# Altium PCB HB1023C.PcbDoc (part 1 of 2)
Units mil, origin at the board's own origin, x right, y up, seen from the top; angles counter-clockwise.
Board outline 1895.03 x 2760.94 mil, 2 copper layers (Top Layer, Bottom Layer); 83 components, 64 nets, 266 pads, 261 vias.
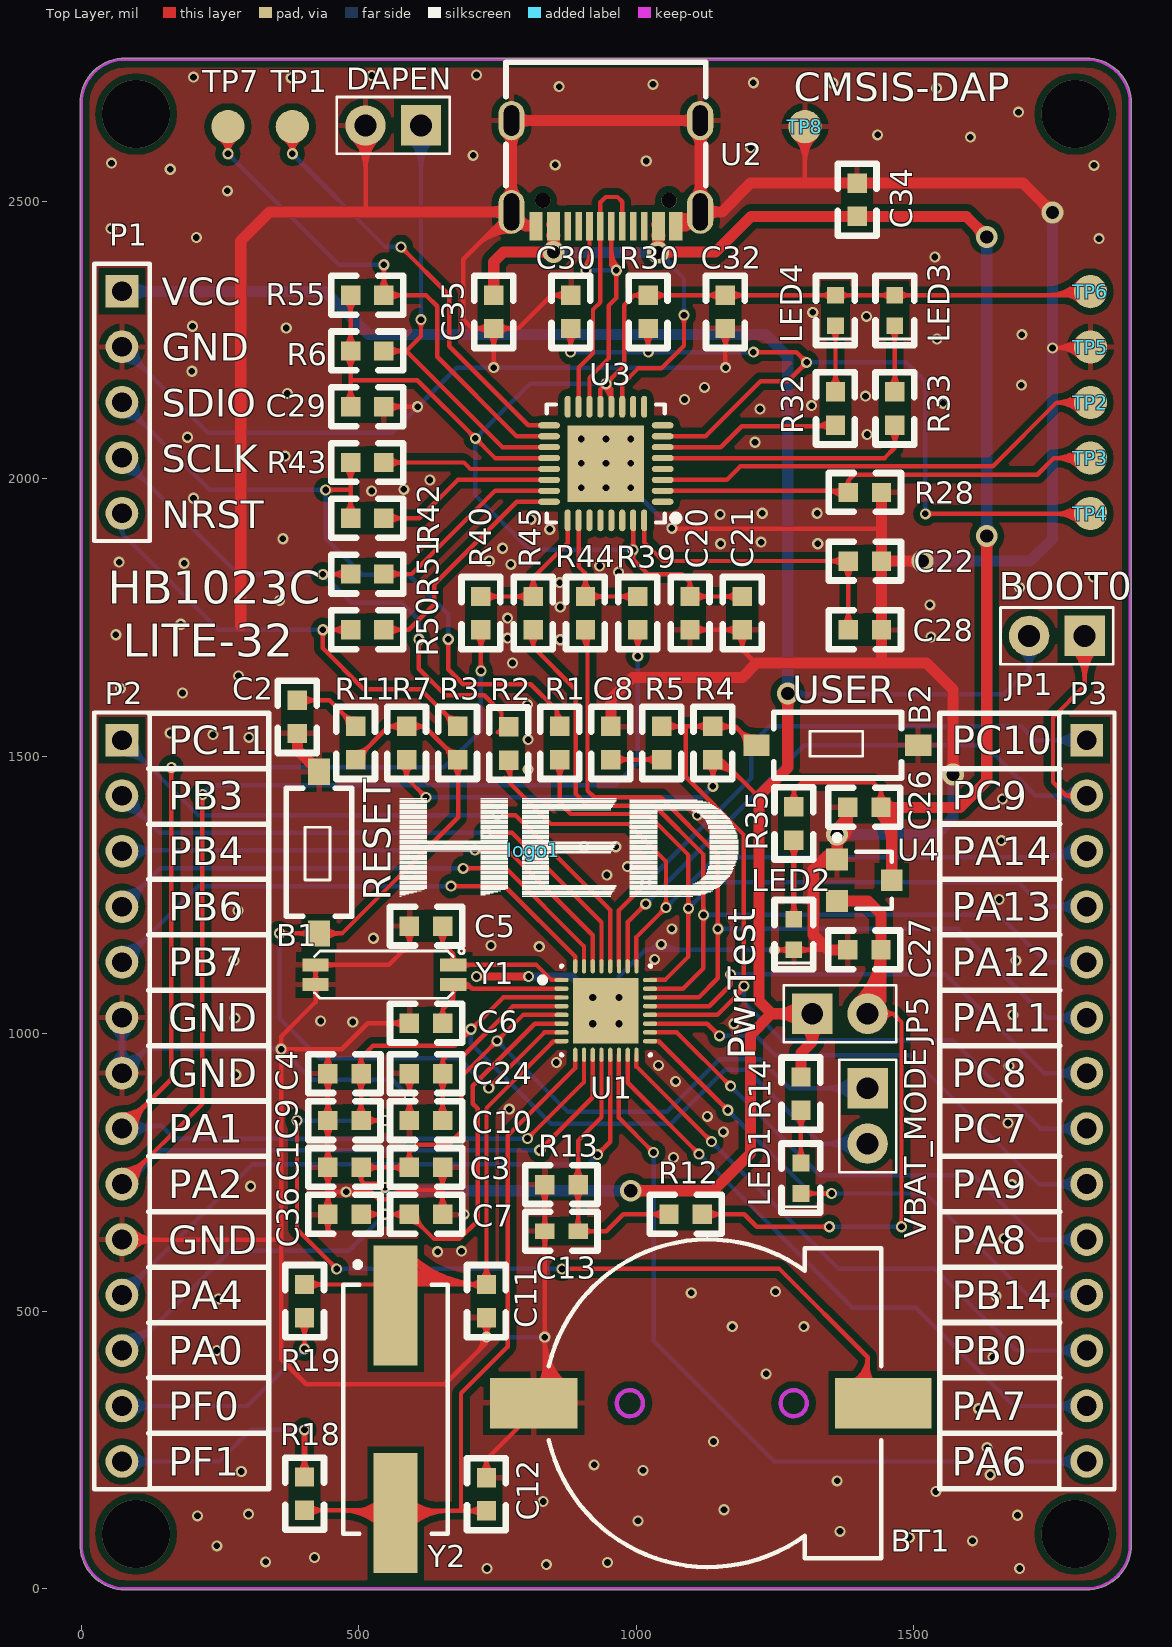
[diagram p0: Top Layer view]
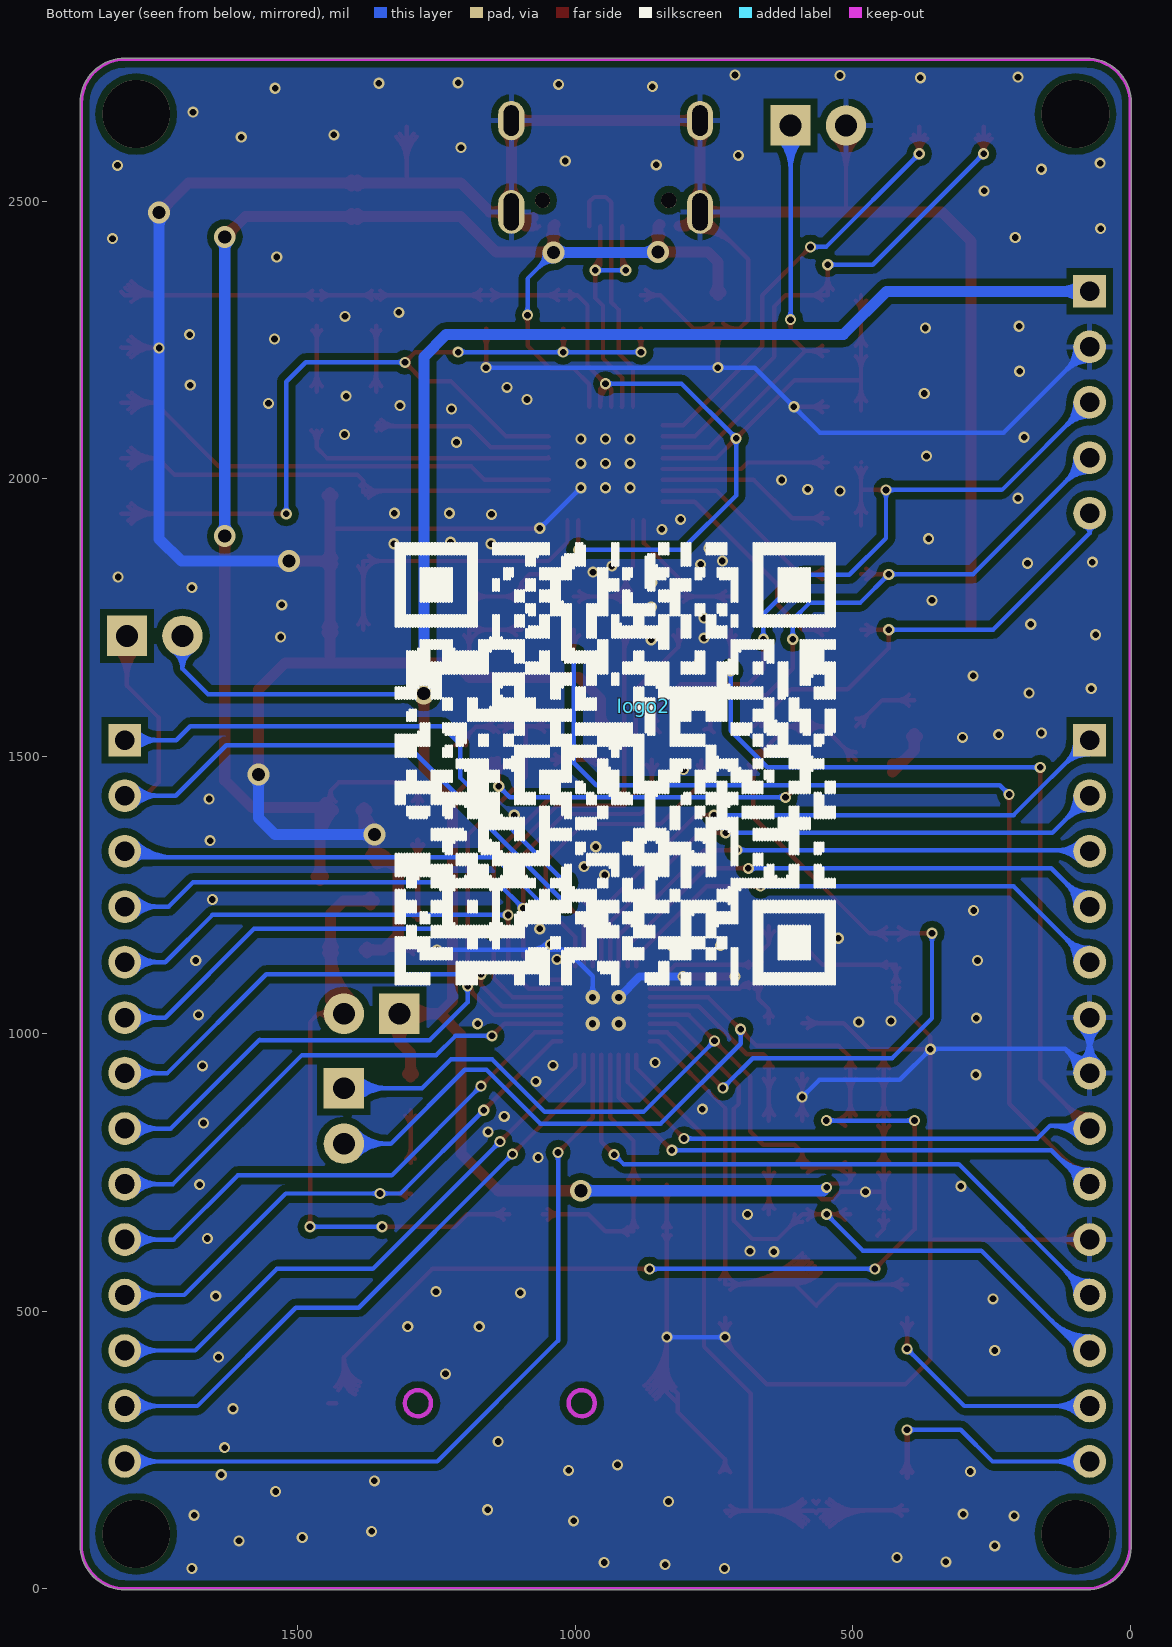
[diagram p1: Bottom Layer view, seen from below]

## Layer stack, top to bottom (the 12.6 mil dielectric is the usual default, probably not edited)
Top Layer: signal copper 1.4
Dielectric: dielectric 12.6, FR-4, Dk 4.8
Bottom Layer: signal copper 1.4

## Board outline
77.95,-2.51 ccw(c78,0) 78.37,-2.49 ccw(c78.74,0) 78.74,-2.51 1811.02,-2.51 ccw(c1811,79) 1892.52,79 ccw(c1890,79) 1892.28,80.06 1892.28,2676.72 ccw(c1889.8,2677.17) 1892.32,2677.17 ccw(c1811.06,2677.17) 1811.06,2758.42 ccw(c1811.06,2755.91) 1811.05,2758.42 ccw(c1811.02,2755.91) 1811.02,2758.42 78.74,2758.42 ccw(c78.74,2677.17) -2.52,2677.17 ccw(c0,2677.17) -2.51,2677.14 -2.51,81.02 cw(c79.5,79.5) -2.51,81.05 -2.51,81.02 ccw(c79.5,79.5)

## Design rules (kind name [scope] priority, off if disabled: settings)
Clearance [(IsPad and InComponent('U1'))] p1: gap=7
Clearance Clearance_poly [(InPolygon)] p2: gap=12
Clearance Clearance_CN [(IsPad and InComponent('P2','P3','U2'))] p3: gap=6
Clearance Clearance_Pad [All] p4: gap=7
ComponentClearance [All] p1: gap=0 collisioncheckmode=3 verticalgap=0 showdistances=FALSE
HoleSize [All] p1: absolutevalues=TRUE maxlimit=130 minlimit=1 maxpercent=80.000 minpercent=20.000
MinimumSolderMaskSliver [All] p1: minsoldermaskwidth=0
PolygonConnect PolygonConnect_Pads [IsPad] p1: connectstyle=Relief reliefconductorwidth=10 reliefentries=4 polygonreliefangle="90 Angle"
PolygonConnect [All] p2: connectstyle=Direct reliefconductorwidth=10 reliefentries=4 polygonreliefangle="90 Angle"
RoutingVias [All] p1: holewidth=12 width=20 viastyle="Through Hole" minholewidth=10 minwidth=18 maxholewidth=300 maxwidth=500
SilkToSilkClearance [All] p1: silktosilkclearance=0
SilkscreenOverComponentPads [IsPad] p1: minsilkscreentomaskgap=0
SolderMaskExpansion [All] p1: expansion=4
TestPointUsage [All] p1: valid=0 allowmultiple=FALSE
Testpoint [(IsPad And (OnTopLayer Or OnBottomLayer))] p1: side=3 testpointundercomponent=TRUE minsize=40 maxsize=100 preferedsize=60 minholesize=0 maxholesize=40 preferedholesize=32 testpointgrid=1 style=297 order=0-112345678
Width [All] p1: maxlimit=20 minlimit=8 preferedwidth=8
19 further rules are at their usual default settings.

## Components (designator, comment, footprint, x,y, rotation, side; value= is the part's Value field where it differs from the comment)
B1 "TS-1101-C-W" 按键_TS-1101-C-W 428,1472 r270 top
B2 "TS-1101-C-W" 按键_TS-1101-C-W 1508,1519.94 r180 top
BT1 "CR1220电池座" CR1220 1445.05,334 r180 top
C1 "10u" 0603#1 444,759 r0 top
C2 "0.1u" 0603#1 389,1601 r270 top
C3 "0.1u" 0603#1 651,759 r180 top
C4 "1u" 0603#1 444,928 r0 top
C5 "10p" 0603#1 591,1194 r0 top
C6 "10p" 0603#1 591,1019 r0 top
C7 "1u" 0603#1 651,674.5 r180 top
C8 "0.1u" 0603#1 954,1554 r270 top
C9 "0.1u" 0603#1 444,843.5 r0 top
C10 "1u" 0603#1 651,843.5 r180 top
C11 "DNP" 0603#1 730,548 r270 top
C12 "DNP" 0603#1 730,140 r90 top
C13 "0.1u" 0603#2 835,644 r0 top
C20 "1u" 0603#1 1096.8,1728 r90 top
C21 "10n" 0603#1 1191,1728 r90 top
C22 "4.7u" 0603#1 1442,1851.75 r180 top
C24 "0.1u" 0603#1 651,928 r180 top
C26 "10u" 0603#1 1381,1408 r0 top
C27 "10u" 0603#1 1381,1151 r0 top
C28 "0.1u" 0603#1 1442,1728 r180 top
C29 "0.1u" 0603#1 545,2130 r180 top
C30 "0.1u" 0603#1 882.17,2271 r90 top
C32 "1u" 0603#1 1160.5,2331 r270 top
C34 "0.1u" 0603#1 1398,2533 r270 top
C35 "1u" 0603#1 743,2331 r270 top
C36 "0.1u" 0603#1 444,674.5 r0 top
DAPEN "Header 1x2" HEADER_1X2_2.54 562,2637 r180 top
JP1 "Header 1x2" HEADER_1X2_2.54 1758,1717 r180 top
JP5 "Header 1x2" HEADER_1X2_2.54 1367,1036 r0 top
LED1 "LED_G" "0603 - p" 1296.78,767 r270 top
LED2 "LED_R" 0603-P 1284,1206 r270 top
LED3 "LED_G" 0603-P 1466,2331 r270 top
LED4 "LED_R" 0603-P 1359,2331 r270 top
logo1 "logo" LOGO 815,1331 r0 top
logo2 "SIGN" SIGN 877,1590 r270 bottom locked
P1 "Header 1x5" HDR1X5_2.54 73,2338 r270 top
P2 "Header 14" HDR1X14 73,1529 r270 top
P3 "Header 14" HDR1X14 1812,1529 r270 top
R1 "470R" 0603#1 862,1494 r90 top
R2 "470R" 0603#1 770,1493 r90 top
R3 "470R" 0603#1 678,1494 r90 top
R4 "4.7k" 0603#1 1138,1554 r270 top
R5 "10R" 0603#1 1046,1494 r90 top
R6 "4.7K" 0603#1 545,2230.5 r180 top
R7 "10K" 0603#1 586,1494 r90 top
R11 "10R" 0603#1 494,1494 r90 top
R12 "10K" 0603#1 1059,674.5 r0 top
R13 "10K" 0603#1 895,728 r180 top
R14 "510R" 0603#1 1296.78,862 r90 top
R18 "0R" 0603#1 402,141 r90 top
R19 "0R" 0603#1 402,548 r270 top
R28 "DNP" 0603#1 1442,1975.5 r180 top
R30 "DNP" 0603#1 1021.33,2331 r270 top
R32 "1K" 0603#1 1359,2097 r90 top
R33 "1K" 0603#1 1466,2097 r90 top
R35 "1K" 0603#1 1284,1349 r90 top
R39 "0R" 0603#1 1002.6,1788 r270 top
R40 "0R" 0603#1 720,1788 r270 top
R42 "150R" 0603#1 545,1929 r180 top
R43 "150R" 0603#1 545,2029.5 r180 top
R44 "DNP" 0603#1 908.4,1788 r270 top
R45 "DNP" 0603#1 814.2,1788 r270 top
R50 "150R" 0603#1 545,1728 r180 top
R51 "150R" 0603#1 545,1828.5 r180 top
R55 "4.7K" 0603#1 485,2331 r0 top
TP1 "TEST_POINT" TEST_POINT 385,2672.78 r90 top
TP2 "TEST_POINT" TEST_POINT 1823.45,2175.5 r90 top
TP3 "TEST_POINT" TEST_POINT 1823.45,2075.5 r90 top
TP4 "TEST_POINT" TEST_POINT 1823.45,1975.5 r90 top
TP5 "TEST_POINT" TEST_POINT 1823.45,2275.5 r90 top
TP6 "TEST_POINT" TEST_POINT 1823.45,2375.5 r90 top
TP7 "TEST_POINT" TEST_POINT 226,2639.78 r180 top
TP8 "TEST_POINT" TEST_POINT 1309,2672.78 r90 top
U1 "" QFN_32N_4X4 945.13,1041.72 r0 top locked
U2 "TYPE-C-16P" HED-KH-TYPE-C-16P 1115.25,2481.06 r180 top locked
U3 "CIU98_H" HED-QFN-32_5x5x05P 945.16,2027.64 r90 top locked
U4 "ME6210A33M3G" SOT-23-3 1407,1279 r270 top
VBAT_MODE "Header 1x2" HEADER_1X2_2.54 1417,851.78 r270 top
Y1 "M6-32.768KHz 12.5pF" XTAL-MC146 670,1123.93 r180 top
Y2 "DNP" XTAL_HC49/SMD 566,323 r270 top

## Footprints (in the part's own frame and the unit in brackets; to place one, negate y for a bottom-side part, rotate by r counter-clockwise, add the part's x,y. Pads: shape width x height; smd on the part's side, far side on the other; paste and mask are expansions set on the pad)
0603#1 [mil]
  rect 35x35 smd: 1(0,0) 2(60,0)
  silkscreen extent -35,-35 95,35
0603#2 [mil]
  rect 35x27.56 smd: 1(0,0) 2(60,0)
  silkscreen extent -35,-35 95,35
"0603 - p" [mil]
  rect 30x30 smd: 1(0,0) 2(55,0)
  silkscreen extent -35,-35 90,35, body extent 1,-15 60,15, height 10
0603-P [mil]
  rect 30x30 smd: 1(0,0) 2(55,0)
  silkscreen extent -35,-35 90,35, body extent 1,-15 60,15, height 10
CR1220 [mm]
  rect 4.4x2.3 smd: 1(0,0)
  rect 4x2.3 smd: 2(16,0)
  Keep-Out Layer circle w0.203: c11.6,0 r0.6
  Keep-Out Layer circle w0.203: c4.1,0 r0.6
  silkscreen extent 0.1,-7.5 15.31,7.5
HDR1X5_2.54 [mm]
  rect 1.5x1.5 hole 0.9: 1(0,0)
  round 1.5 hole 0.9: 2(2.54,0) 3(5.08,0) 4(7.62,0) 5(10.16,0)
  silkscreen extent -1.27,-1.27 11.43,1.27
HDR1X14 [mm] "Connector; Header; 14 Position"
  rect 1.5x1.5 hole 0.9: 1(0,0)
  round 1.5 hole 0.9: 2(2.54,0) 3(5.08,0) 4(7.62,0) 5(10.16,0) 6(12.7,0) 7(15.24,0) 8(17.78,0) 9(20.32,0) 10(22.86,0) 11(25.4,0) 12(27.94,0) 13(30.48,0) 14(33.02,0)
  silkscreen extent -1.27,-1.27 34.29,1.27
HEADER_1X2_2.54 [mm]
  rect 1.85x1.85 / inner round 1.85 / far side rect 1.85x1.85 hole 1: 1(-1.27,0)
  round 1.85 hole 1: 2(1.27,0)
  silkscreen extent -2.58,-1.3 2.58,1.3, body extent -2.67,-1.3 2.58,1.3, height 8.38
HED-KH-TYPE-C-16P [mm]
  oval 1.2x2 hole 0.7 slot 1.7 at 90 deg: 1(0,0) 2(8.64,0)
  oval 1.2x1.8 hole 0.7 slot 1.4 at 90 deg: 3(0,-4.18) 4(8.64,-4.18)
  rect 0.3x1.3 smd: A1(0.97,0.65) A4(1.77,0.65) A5(3.07,0.65) A6(4.07,0.65) A7(4.57,0.65) A8(5.57,0.65) A9(6.87,0.65) A12(7.67,0.65) B1(7.37,0.65) B4(6.57,0.65) B5(6.07,0.65) B6(5.07,0.65) B7(3.57,0.65) B8(2.57,0.65) B9(2.07,0.65) B12(1.27,0.65)
  round 0.7 hole 0.7 unplated: ""(1.43,-0.53) ""(7.21,-0.53)
  silkscreen extent -0.25,-6.84 8.89,-1.19
HED-QFN-32_5x5x05P [mm]
  oval 0.28x1 smd: 1(-1.75,-2.6) 2(-1.25,-2.6) 3(-0.75,-2.6) 4(-0.25,-2.6) 5(0.25,-2.6) 6(0.75,-2.6) 7(1.25,-2.6) 8(1.75,-2.6) 17(1.75,2.6) 18(1.25,2.6) 19(0.75,2.6) 20(0.25,2.6) 21(-0.25,2.6) 22(-0.75,2.6) 23(-1.25,2.6) 24(-1.75,2.6)
  oval 1x0.28 smd: 9(2.6,-1.75) 10(2.6,-1.25) 11(2.6,-0.75) 12(2.6,-0.25) 13(2.6,0.25) 14(2.6,0.75) 15(2.6,1.25) 16(2.6,1.75) 25(-2.6,1.75) 26(-2.6,1.25) 27(-2.6,0.75) 28(-2.6,0.25) 29(-2.6,-0.25) 30(-2.6,-0.75) 31(-2.6,-1.25) 32(-2.6,-1.75)
  rect 3.5x3.5 smd: 33(0,0)
  silkscreen extent -2.7,-3.35 2.7,2.7
LOGO [mil]
  silkscreen extent -241,-83 369,93
QFN_32N_4X4 [mm]
  oval 0.65x0.2 smd: 1(-2.025,1.4) 2(-2.025,1) 3(-2.025,0.6) 4(-2.025,0.2) 5(-2.025,-0.2) 6(-2.025,-0.6) 7(-2.025,-1) 8(-2.025,-1.4) 17(2.025,-1.4) 18(2.025,-1) 19(2.025,-0.6) 20(2.025,-0.2) 21(2.025,0.2) 22(2.025,0.6) 23(2.025,1) 24(2.025,1.4)
  oval 0.2x0.65 smd: 9(-1.4,-2.025) 10(-1,-2.025) 11(-0.6,-2.025) 12(-0.2,-2.025) 13(0.2,-2.025) 14(0.6,-2.025) 15(1,-2.025) 16(1.4,-2.025) 25(1.4,2.025) 26(1,2.025) 27(0.6,2.025) 28(0.2,2.025) 29(-0.2,2.025) 30(-0.6,2.025) 31(-1,2.025) 32(-1.4,2.025)
  rect 3x3 smd: 33(0,0)
  silkscreen extent -3.02,-2.05 2.05,2.05, body extent -2.05,-2.05 2.05,2.05, height 0.8
SIGN [mil]
  silkscreen extent -294,-446 501,344
SOT-23-3 [mm]
  rect 1x1 smd: 1(-0.889,-1.143) 2(1.011,-1.143) 3(0.061,1.357)
  silkscreen extent -2.01,-1.27 1.36,1.36, body extent -1.39,-1.29 1.51,1.51, height 1.2
TEST_POINT [mil]
  round 60 smd: 1(-38,5)
XTAL-MC146 [mm]
  rect 1.2x0.6 smd mask+0.05: 1(0,0) 2(6.3,0) 3(6.3,0.9) 4(0,0.9)
  silkscreen extent -0.51,-0.76 6.35,1.52
XTAL_HC49/SMD [mm]
  rect 5.5x2 smd: 1(-4.75,0) 2(4.75,0)
  silkscreen extent -6.75,-2.4 5.7,2.4, body extent -6.7,-2.46 6.7,2.44, height 4
按键_TS-1101-C-W [mm] "星坤品牌"
  rect 1.2x1 smd mask+0.05: 1(0,0) 2(7.4,0)
  silkscreen extent 0.76,-1.5 6.6,1.5

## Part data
B1 U1: library part CIU32L051Kx-QFN32
B2: library part SW-PB, "贴片按键"
BT1: library part Battery, "Multicell Battery"
C1 C13 C36: library part MCD-00009, "Capacitor, MLCC, 4.7uF, 16V, X5R, 10%, 0603, T=0.8mm"
C2 C3 C4 C7 C9 C11 C20 C21 C22 C30 C32 C35: library part MCD-00211, "Capacitor, MLCC, 100nF, 16V, X7R, 10%, 0603, T=0,8mm"
C5 C6: library part MCD-00666, "Capacitor,5.6pF,0.1pF,16V,NPO,0603"
C8: library part MCD-00211, "贴片电容"
C10 C12: library part MCD-00009, "贴片电容33p"
C24 C26: library part MCD-00014, "Capacitor, MLCC, 10uF, 25V, X5R, 10%, 0805, T=0,85mm"
C27 P1: library part SWD, "Header, 1x5, 2,54mm, VR, TH, Height 5.84mm/2.54mm"
C28 C29: library part "Header 14", "Header, 14-Pin"
C34: library part "0603 100nF 10% 50V", "贴片电容"
DAPEN: library part MCD-00683, "Header, 2x1, 2,54mm, VR, TH, Height 5.84mm/2.54mm"
JP1 JP5 VBAT_MODE: library part MCD-00683, "Header, 2x1, 2,54mm, VR, TH, Height 5.84mm/2.54mm - Shunt Fitted by default"
LED1 LED3: library part LED1, "贴片LED 绿色"
LED2 LED4: library part LED1, "贴片LED 红色"
P2 P3: "Header, 14-Pin"
R1 R2 R3 R6 R28 R42 R43 R50 R51 R55: library part Res, "贴片电阻"
R4 R5 R7 R11 R12 R13 R14 R18 R19 R30 R32 R33 R35 R39 R40 R44 R45: library part Res2, "贴片电阻"
U2: library part KH-TYPE-C-16P, "TYPE-C USB接口"
U3: library part CIU98-H, "贴片芯片"
U4: library part ME6210, "贴片LDO3.3V"
Y1: library part MC146, "贴片晶振"
Y2: library part XTAL_32K_NX3215SA, "Crystal 32.768kHz, 6pF, -+20PPM, R=50K, SMD"

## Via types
v1: diameter 20, hole 12, Top Layer to Bottom Layer, tented both sides, 243 vias
v2: diameter 39.37, hole 23.62, Top Layer to Bottom Layer, tented both sides, 10 vias
v3: diameter 122.05, hole 122.05, Top Layer to Bottom Layer, tented both sides, 4 vias
v4: diameter 25.98, hole 12.99, Top Layer to Bottom Layer, 4 vias

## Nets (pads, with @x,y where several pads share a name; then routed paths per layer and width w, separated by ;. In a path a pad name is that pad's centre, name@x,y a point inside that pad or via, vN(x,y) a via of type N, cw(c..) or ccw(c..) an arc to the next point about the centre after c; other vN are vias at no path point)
CMS_STATE: TP1.1 U3.17 | length 967.8
  Top Layer w8: TP1.1@365.51,2613.19 cw(c347.25,2586) v1(380,2586) ; TP1.1@369.97,2619.84 cw(c357.33,2601.01) 380,2601.01 cw(c402.68,2601.01) TP1.1@390.03,2619.84 ; v1@375.76,2590.24 ccw(c365.51,2600.49) 380,2600.49 ccw(c394.48,2600.48) v1@384.24,2590.24 ; TP1.1@380,2634.78 v1(380,2586) ; TP1.1@394.49,2613.19 ccw(c412.75,2586) v1(380,2586) ; v1@576,2412 cw(c576,2397.51) 586.24,2407.76 cw(c596.49,2418) v1@582,2418 ; v1(576,2418) 663,2331 663,2239 805.46,2096.54 U3.17@842.8,2096.54
  Bottom Layer w8: v1@380,2580 cw(c380,2565.51) 390.24,2575.76 cw(c400.49,2586) v1@386,2586 ; v1(380,2586) 548,2418 v1(576,2418) ; v1@571.76,2413.76 ccw(c561.51,2403.51) 561.51,2418 ccw(c561.51,2432.49) v1@571.76,2422.24
GND: B1.1 B2.1 BT1.2 C1.1 C2.2 C3.1 C4.1 C5.1 C6.1 C7.1 C8.1 C9.1 C10.2 C11.2 C12.2 C13.1 C20.1 C21.1 C22.1 C24.2 C26.1 C27.1 C28.1 C29.1 C30.2 C32.2 C34.1 C35.2 C36.1 DAPEN.2 LED2.2 P1.2 P2.6 P2.7 P2.10 R13.2 R28.1 TP5.1 TP8.1 U1.33 U2.1 U2.2 U2.3 U2.4 U2.A1 U2.A12 U2.B1 U2.B12 U3.33 U4.1 Y1.2 Y1.3 | length 18990.4
  Top Layer w8: P2.10@66,629 P2.10@73,629 ; P2.6@73,1029 P2.6@76,1032 ; P2.10@74,629 P2.10@73,629 ; P2.10@85.39,616.61 cw(c115.32,586.68) 115.32,629 cw(c115.32,671.32) P2.10@85.39,641.39 ; P2.10@91.05,610.95 cw(c134.63,567.37) 134.63,629 cw(c134.63,690.63) P2.10@91.05,647.05 ; v1@355.69,967.76 cw(c345.45,957.51) 359.93,957.51 cw(c374.42,957.51) 364.17,967.76 cw(c374.42,957.51) 374.42,972 cw(c374.42,986.49) 364.17,976.24 cw(c374.42,986.49) 359.93,986.49 cw(c345.45,986.49) v1@355.69,976.24 ; Y1.3@416.45,1082.98 cw(c403.11,1069.64) 421.97,1069.64 cw(c440.83,1069.64) Y1.3@427.49,1082.98 ; Y1.3@416.45,1094.02 ccw(c403.11,1107.36) 421.97,1107.36 ccw(c440.83,1107.36) Y1.3@427.49,1094.02 ; Y1.2@416.45,1118.41 cw(c403.11,1105.07) 421.97,1105.07 cw(c440.83,1105.07) Y1.2@427.49,1118.41 ; C36.1@434.45,684.05 ccw(c411.41,707.09) 444,707.09 ccw(c476.59,707.09) C36.1@453.55,684.05 ; C1.1@434.45,749.45 cw(c411.41,726.41) 444,726.41 cw(c476.59,726.41) C1.1@453.55,749.45 ; C1.1@434.45,768.55 ccw(c411.41,791.59) 444,791.59 ccw(c476.59,791.59) C1.1@453.55,768.55 ; C9.1@434.45,833.95 cw(c411.41,810.91) 444,810.91 cw(c476.59,810.91) C9.1@453.55,833.95 ; C9.1@434.45,853.05 ccw(c411.41,876.09) 444,876.09 ccw(c476.59,876.09) C9.1@453.55,853.05 ; C4.1@434.45,918.45 cw(c411.41,895.41) 444,895.41 cw(c476.59,895.41) C4.1@453.55,918.45 ; C4.1@434.45,937.55 ccw(c411.41,960.59) 444,960.59 ccw(c476.59,960.59) C4.1@453.55,937.55 ; C36.1@436.06,663.58 cw(c424.74,648) 444,648 ; Y1.2@439.3,1118.41 cw(c452.64,1105.07) 452.64,1123.93 cw(c452.64,1142.79) Y1.2@439.3,1129.46 ; C36.1@444,674.5 444,648 ; C36.1@444,683.94 C1.1@444,759 C9.1@444,843.5 C4.1@444,928 444,972 ; 446,715 522,715 535,702 555.7,702 571.7,718 651,718 ; C36.1@451.94,663.58 ccw(c463.26,648) 444,648 ; 456,636 444,648 ; v1@472.76,710.76 ccw(c462.51,700.51) 462.51,715 ccw(c462.51,729.49) v1@472.76,719.24 ; v1@481.24,710.76 cw(c491.49,700.51) 491.49,715 cw(c491.49,729.49) v1@481.24,719.24 ; DAPEN.2@489.08,2614.08 cw(c433.74,2558.74) 512,2558.74 cw(c590.26,2558.74) DAPEN.2@534.92,2614.08 ; DAPEN.2@494.73,2619.73 cw(c453.05,2578.05) 512,2578.05 cw(c570.95,2578.05) DAPEN.2@529.27,2619.73 ; DAPEN.2@500.39,2625.39 cw(c472.37,2597.37) 512,2597.37 cw(c551.64,2597.37) DAPEN.2@523.61,2625.39 ; 512,2481.06 DAPEN.2@512,2637 ; C29.1@545,2130 v1(606,2130) ; C29.1@554.55,2120.45 cw(c577.59,2097.41) 577.59,2130 cw(c577.59,2162.59) C29.1@554.55,2139.55 ; C10.2@581.45,853.05 ccw(c558.41,876.09) 591,876.09 ccw(c623.59,876.09) C10.2@600.55,853.05 ; C24.2@581.45,918.45 cw(c558.41,895.41) 591,895.41 cw(c623.59,895.41) C24.2@600.55,918.45 ; C6.1@581.45,1009.45 ccw(c558.41,986.41) 558.41,1019 ccw(c558.41,1051.59) C6.1@581.45,1028.55 ; C5.1@581.45,1184.45 cw(c558.41,1161.41) 591,1161.41 cw(c623.59,1161.41) C5.1@600.55,1184.45 ; v1@586.76,881.76 cw(c576.52,871.51) 591,871.51 cw(c605.49,871.51) v1@595.24,881.76 ; v1@586.76,890.24 ccw(c576.52,900.49) 591,900.49 ccw(c605.49,900.49) v1@595.24,890.24 ; C10.2@591,843.5 v1(591,886) C24.2@591,928 ; C6.1@591,1019 516,1019 469,972 v1(359.93,972) ; C5.1@591,1194 591,1161 553.93,1123.93 Y1.2@421.97,1123.93 Y1.3@421.97,1088.5 421.97,1056.97 359.93,994.93 v1(359.93,972) ; v1@601.76,2125.76 ccw(c591.51,2115.51) 591.51,2130 ccw(c591.51,2144.49) v1@601.76,2134.24 ; C7.1@641.45,684.05 ccw(c618.41,707.09) 651,707.09 ccw(c683.59,707.09) C7.1@660.55,684.05 ; C3.1@641.45,749.45 cw(c618.41,726.41) 651,726.41 cw(c683.59,726.41) C3.1@660.55,749.45 ; C7.1@651,674.5 651,718 ; C3.1@651,759 651,718 ; 711.23,2419.23 cw(c775.1,2355.37) U2.2@775.1,2445.69 ; 712.69,425.69 ccw(c685.37,453) v1@724,453 ; C12.2@720.45,209.55 ccw(c697.41,232.59) 730,232.59 ccw(c762.59,232.59) C12.2@739.55,209.55 ; C11.2@720.45,478.45 cw(c697.41,455.41) 730,455.41 cw(c762.59,455.41) C11.2@739.55,478.45 ; 724.89,2432.89 cw(c775.1,2382.68) U2.2@775.1,2453.69 ; v1@725.76,457.24 ccw(c715.51,467.48) 730,467.48 ccw(c744.48,467.48) v1@734.24,457.24 ; C12.2@726.22,212.96 ccw(c724.75,218) 730,218 ; 726.34,439.34 ccw(c712.69,453) v1@732,453 ; C11.2@730,488 v1(730,453) 730,443 655,368 405,368 359.93,413.07 359.93,629 ; C35.2@733.45,2280.55 cw(c710.41,2303.59) 710.41,2271 cw(c710.41,2238.41) 733.45,2261.45 cw(c710.41,2238.41) 743,2238.41 cw(c775.59,2238.41) 752.55,2261.45 cw(c775.59,2238.41) 775.59,2271 cw(c775.59,2303.59) C35.2@752.55,2280.55 ; C12.2@733.78,212.96 cw(c735.25,218) 730,218 ; 738.55,2446.55 cw(c775.1,2410) U2.2@775.1,2461.69 ; v1@738.76,2204.74 ccw(c728.51,2214.99) 743,2214.99 ccw(c757.48,2214.99) v1@747.24,2204.74 ; v1(743,2200.5) C35.2@743,2271 ; U2.2@787.69,2481.06 773.06,2481.06 688,2396 688,2287 704,2271 C35.2@743,2271 ; BT1.2@819.4,363.19 ccw(c781.75,400.84) 835,400.84 ; BT1.2@825.06,357.53 ccw(c801.07,381.52) 835,381.52 ; R13.2@825.45,718.45 cw(c802.41,695.41) 835,695.41 cw(c867.59,695.41) R13.2@844.55,718.45 ; C13.1@828.08,637.08 cw(c811.39,620.39) 835,620.39 cw(c858.61,620.39) C13.1@841.92,637.08 ; C13.1@828.08,650.92 ccw(c811.39,667.61) 835,667.61 ccw(c858.61,667.61) C13.1@841.92,650.92 ; v1@830.76,448.76 cw(c820.51,438.51) 835,438.51 cw(c849.48,438.51) v1@839.24,448.76 ; v1@830.76,457.24 ccw(c820.51,467.49) 835,467.49 ccw(c849.48,467.48) v1@839.24,457.24 ; 835,383.59 ccw(c890.94,383.59) BT1.2@854.61,341.05 ; 835,400.94 ccw(c905.75,400.94) BT1.2@859.81,347.14 ; 835,418.29 ccw(c920.57,418.29) BT1.2@865,353.22 ; 835,435.64 ccw(c935.38,435.64) BT1.2@870.2,359.31 ; R13.2@835,728 v1(835,453) ; BT1.2@837.5,373.37 815.13,351 BT1.2@815.13,334 ; C30.2@872.62,2321.45 ccw(c849.57,2298.41) 849.57,2331 ccw(c849.57,2363.59) C30.2@872.62,2340.55 ; BT1.2@875.39,365.39 cw(c950.2,453) v1(835,453) ; C30.2@882.17,2331 847,2331 787,2271 C35.2@743,2271 ; C8.1@944,1543 C8.1@944,1543.4 ; v1@1064,1910 1441,1910 ; U2.B12@1065.25,2455.46 U2.B12@1069,2451.71 ; v1@1068.24,1906.76 cw(c1076.07,1898.93) 1076.07,1910 ; v1@1068.24,1915.24 ccw(c1080.9,1927.9) 1080.9,1910 ; C20.1@1096.8,1728 C21.1@1191,1728 1191,1692 1216,1667 ; C20.1@1106.35,1718.45 cw(c1129.39,1695.41) 1129.39,1728 cw(c1129.39,1760.59) C20.1@1106.35,1737.55 ; C32.2@1150.95,2261.45 cw(c1127.91,2238.41) 1160.5,2238.41 cw(c1193.09,2238.41) C32.2@1170.05,2261.45 ; v1@1156.76,2204.74 ccw(c1147.72,2213.78) 1160.5,2213.78 ; 1160.5,2216.19 ccw(c1176.69,2216.19) v1@1165.24,2204.74 ; C32.2@1160.5,2271 1160.5,2201 v1(1161,2200.5) ; C21.1@1181.45,1737.55 cw(c1158.41,1760.59) 1158.41,1728 cw(c1158.41,1695.41) 1181.45,1718.45 cw(c1158.41,1695.41) 1191,1695.41 cw(c1223.59,1695.41) C21.1@1200.55,1718.45 ; v1@1246,1151 LED2.2@1284,1151 ; v1@1253.24,1146.76 cw(c1263.49,1136.51) 1263.49,1151 cw(c1263.49,1165.49) v1@1253.24,1155.24 ; LED2.2@1276.22,1143.22 ccw(c1257.44,1124.44) 1257.44,1151 ccw(c1257.44,1177.56) LED2.2@1276.22,1158.78 ; LED2.2@1285,1152 LED2.2@1284,1151 ; TP8.1@1285.62,2616.39 cw(c1241.23,2572.01) 1304,2572.01 cw(c1366.77,2572.01) TP8.1@1322.39,2616.39 ; TP8.1@1291.27,2622.05 cw(c1260.54,2591.32) 1304,2591.32 cw(c1347.46,2591.32) TP8.1@1316.73,2622.05 ; LED2.2@1291.78,1143.22 cw(c1310.56,1124.44) 1310.56,1151 cw(c1310.56,1177.56) LED2.2@1291.78,1158.78 ; 1304,2533 TP8.1@1304,2634.78 ; 1346,1151 LED2.2@1284,1151 ; C34.1@1388,2523 C34.1@1398,2533 ; v1(1750,2236) 1816.94,2236 TP5.1@1818.45,2237.5 ; v1@1752.05,2236 ccw(c1752.05,2303.9) TP5.1@1800.06,2255.89 ; v1@1754.24,2231.76 cw(c1764.49,2221.51) 1764.49,2236 cw(c1764.49,2250.49) v1@1754.24,2240.24 ; v1@1759.31,2236 cw(c1759.31,2178.37) TP5.1@1800.06,2219.12 ; 1771.36,2236 ccw(c1771.36,2284.59) TP5.1@1805.72,2250.23 ; 1778.62,2236 cw(c1778.62,2197.68) TP5.1@1805.72,2224.78 ; P2.10@73,629 359.93,629 ; 359.93,629 v1(359.93,972) ; 730,218 730,233 815.13,318.13 BT1.2@815.13,334 ; BT1.2@815.13,334 835,353.87 v1(835,453)
  Top Layer w15: v1(712,1103) v1(806,1103)
  Top Layer w20: 287,1736 287,2429 339.06,2481.06 U2.2@775.1,2481.06 ; C2.2@383.7,1535.7 cw(c370.89,1522.89) 389,1522.89 cw(c407.11,1522.89) C2.2@394.3,1535.7 ; C2.2@389,1541 389,1511 B1.1@428,1472 ; 404.75,1495.25 ccw(c428,1518.51) B1.1@428,1485.62 ; U2.2@765.46,2471.42 ccw(c742.21,2448.17) 742.21,2481.06 ccw(c742.21,2513.94) U2.2@765.46,2490.69 ; U2.2@765.46,2506.44 ccw(c742.21,2529.69) 775.1,2529.69 ccw(c807.98,2529.69) U2.2@784.73,2506.44 ; U2.4@765.46,2624.18 cw(c742.21,2600.92) 775.1,2600.92 cw(c807.98,2600.92) U2.4@784.73,2624.18 ; U2.4@784.73,2635.99 cw(c807.98,2612.74) 807.98,2645.62 cw(c807.98,2678.51) U2.4@784.73,2655.25 ; U2.2@787.25,2471.46 ccw(c813.28,2484.64) U2.A12@813.28,2455.46 800.69,2455.46 U2.2@775.1,2481.06 ; C8.1@948.7,1559.3 ccw(c935.09,1572.91) 954.33,1572.91 ; C8.1@954.33,1557.33 954.33,1603.33 993,1642 1191,1642 1216,1667 1217,1668 1523,1668 1571,1620 v2(1571,1467) ; U2.A1@1075.87,2471.23 ccw(c1087.38,2508.93) U2.1@1115.25,2481.06 ; U2.1@1103.1,2471.46 cw(c1077.07,2484.64) U2.A1@1077.06,2455.46 1089.65,2455.46 U2.1@1115.25,2481.06 ; U2.1@1105.62,2506.44 ccw(c1082.37,2529.69) 1115.25,2529.69 ccw(c1148.14,2529.69) U2.1@1124.88,2506.44 ; U2.3@1105.62,2624.18 cw(c1082.37,2600.92) 1115.25,2600.92 cw(c1148.14,2600.92) U2.3@1124.88,2624.18 ; U2.3@1105.62,2635.99 ccw(c1082.37,2612.74) 1082.37,2645.62 ccw(c1082.37,2678.51) U2.3@1105.62,2655.25 ; U2.1@1124.88,2471.42 cw(c1148.14,2448.17) 1148.14,2481.06 cw(c1148.14,2513.94) U2.1@1124.88,2490.69 ; 1324.5,1301.5 cw(c1343.48,1282.52) U4.1@1357.09,1305.65 ; 1337.93,1314.93 cw(c1360.68,1292.18) U4.1@1362.62,1324.3 ; U4.1@1342.77,1319.77 cw(c1357.02,1305.53) U4.1@1367.23,1322.89 ; U4.1@1355.15,1307.15 ccw(c1338.62,1290.62) 1338.62,1314 ccw(c1338.62,1337.38) 1355.15,1320.85 ccw(c1338.62,1337.38) 1362,1337.38 ccw(c1385.38,1337.38) U4.1@1368.85,1320.85 ; v2@1355.15,1352.15 cw(c1338.62,1335.62) 1362,1335.62 cw(c1385.38,1335.62) v2@1368.85,1352.15 ; v2@1357.26,1367.45 ccw(c1334.5,1408) C26.1@1381,1408 1381,1378 v2(1362,1359) U4.1@1362,1314 1337,1314 1319,1296 1319,1178 1346,1151 C27.1@1381,1151 C27.1@1380,1152 ; v2@1367.05,1350.01 ccw(c1353.67,1373.84) 1381,1373.84 ; C27.1@1375.7,1145.7 ccw(c1362.89,1132.89) 1362.89,1151 ccw(c1362.89,1169.11) C27.1@1375.7,1156.3 ; C26.1@1375.7,1402.7 cw(c1362.89,1389.89) 1381,1389.89 cw(c1399.11,1389.89) C26.1@1386.3,1402.7 ; C34.1@1392.7,2527.7 ccw(c1379.89,2514.89) 1379.89,2533 ccw(c1379.89,2551.11) C34.1@1392.7,2538.3 ; C34.1@1403.3,2527.7 cw(c1416.11,2514.89) 1416.11,2533 cw(c1416.11,2551.11) C34.1@1403.3,2538.3 ; C28.1@1436.7,1722.7 cw(c1423.89,1709.89) 1442,1709.89 cw(c1460.11,1709.89) C28.1@1447.3,1722.7 ; C28.1@1436.7,1733.3 ccw(c1423.89,1746.11) 1442,1746.11 ccw(c1460.11,1746.11) C28.1@1447.3,1733.3 ; C22.1@1436.7,1846.45 cw(c1423.89,1833.64) 1442,1833.64 cw(c1460.11,1833.64) 1447.3,1846.45 cw(c1460.11,1833.64) 1460.11,1851.75 cw(c1460.11,1869.86) 1447.3,1857.05 cw(c1460.11,1869.86) 1442,1869.86 cw(c1423.89,1869.86) C22.1@1436.7,1857.05 ; R28.1@1436.7,1970.2 cw(c1423.89,1957.39) 1442,1957.39 cw(c1460.11,1957.39) R28.1@1447.3,1970.2 ; 1442,1669 C28.1@1442,1728 C22.1@1442,1851.75 ; R28.1@1442,1975.5 C22.1@1442,1851.75 ; v2@1508.9,1844.9 ccw(c1492.37,1828.37) 1492.37,1851.75 ccw(c1492.37,1875.13) v2@1508.9,1858.6 ; v2(1515.75,1851.75) C22.1@1442,1851.75 ; v2@1564.15,1473.85 ccw(c1547.62,1490.38) 1571,1490.38 ccw(c1594.38,1490.38) v2@1577.85,1473.85 ; v2@1740.31,2480 ccw(c1716.93,2480) 1733.47,2496.53 ccw(c1750,2513.07) v2@1750,2489.68 ; v2(1750,2480) 1697,2533 C34.1@1398,2533 1304,2533 1206,2533 1154.06,2481.06 U2.1@1115.25,2481.06 ; U2.2@775.1,2481.06 U2.4@775.1,2645.62 U2.3@1115.25,2645.62 U2.1@1115.25,2481.06
  Bottom Layer w8: P2.7@54.95,947.05 ccw(c11.37,990.63) 73,990.63 ccw(c134.63,990.63) P2.7@91.05,947.05 ; P2.6@54.95,1010.95 cw(c11.37,967.37) 73,967.37 cw(c134.63,967.37) P2.6@91.05,1010.95 ; P2.10@57,629 P2.10@73,629 ; P2.7@60.61,941.39 ccw(c30.69,971.32) 73,971.32 ccw(c115.32,971.32) P2.7@85.39,941.39 ; P2.6@60.61,1016.61 cw(c30.69,986.68) 73,986.68 cw(c115.32,986.68) P2.6@85.39,1016.61 ; P2.7@68,929 P2.7@73,929 ; P2.7@73,946.53 ccw(c73,988.84) 102.92,958.92 ccw(c132.84,929) P2.7@90.53,929 ; P2.7@73,954.53 ccw(c73,1016.16) 116.58,972.58 ccw(c160.16,929) P2.7@98.53,929 ; P2.6@73,1029 P2.7@73,929 ; P1.2@73,2212.47 cw(c73,2150.84) 116.58,2194.42 cw(c160.16,2238) P1.2@98.53,2238 ; P1.2@73,2220.47 cw(c73,2178.16) 102.92,2208.08 cw(c132.84,2238) P1.2@90.53,2238 ; P1.2@73,2238 228,2083 559,2083 v1(606,2130) 676.5,2200.5 v1(743,2200.5) v1(1161,2200.5) ; 343.03,973 cw(c343.03,955.1) v1@355.69,967.76 ; 347.86,973 ccw(c347.86,984.07) v1@355.69,976.24 ; v1@359.93,966 cw(c359.93,951.51) 370.17,961.76 cw(c380.42,972) v1@365.93,972 ; v1@585,886 ccw(c570.52,886) 580.76,896.24 ccw(c591,906.49) v1@591,892 ; v1(591,886) 560,917 414.93,917 v1(359.93,972) 358.93,973 117,973 P2.7@73,929 ; v1@600,2130 cw(c585.51,2130) 595.76,2119.76 cw(c606,2109.51) v1@606,2124 ; v1@606,2136 ccw(c606,2150.49) 616.24,2140.24 ccw(c626.49,2130) v1@612,2130 ; v1(730,453) v1(835,453) ; v1@734.24,448.76 cw(c744.48,438.51) 744.48,453 cw(c744.48,467.48) v1@734.24,457.24 ; v1@738.76,2196.26 ccw(c728.51,2186.01) 728.51,2200.5 ccw(c728.51,2214.99) v1@738.76,2204.74 ; v1@747.24,2196.26 cw(c757.48,2186.01) 757.48,2200.5 cw(c757.48,2214.99) v1@747.24,2204.74 ; v1@830.76,448.76 ccw(c820.51,438.51) 820.51,453 ccw(c820.51,467.48) v1@830.76,457.24 ; v4@962.39,1071.7 ccw(c947.04,1087.05) 968.75,1087.05 ccw(c990.46,1087.05) v4@975.11,1071.7 ; v4(968.75,1065.35) 968.75,1103.75 1016,1151 ; v1@990,1978 cw(c990,1963.51) 1000.24,1973.76 cw(c1010.49,1984) v1@996,1984 ; v1(990,1984) v1@1064,1910 ; 1030.5,1151 ccw(c1030.5,1170.14) v1@1046.69,1159.93 ; v1@1039.92,1164.2 cw(c1016,1179.28) 1016,1151 ; v1@1043.59,1159.59 ccw(c1064.31,1180.31) 1064.31,1151 ; v1@1049.24,1165.24 ccw(c1083.63,1199.63) 1083.63,1151 ; 1052.05,1921.95 ccw(c1064,1933.9) v1@1064,1917 ; 1054.46,1919.54 cw(c1045.93,1911) v1@1058,1911 ; v1@1156.76,2196.26 ccw(c1146.51,2186.01) 1146.51,2200.5 ccw(c1146.51,2214.99) v1@1156.76,2204.74 ; v1@1244.76,1146.76 ccw(c1234.51,1136.51) 1234.51,1151 ccw(c1234.51,1165.49) v1@1244.76,1155.24 ; v1@1246,1151 1016,1151
  Bottom Layer w15: v1(806,1103) 883.85,1103 v4(921.5,1065.35) ; v4@916.01,1065.35 ccw(c902.75,1065.35) 912.13,1074.72 ccw(c921.5,1084.1) v4@921.5,1070.84
  Bottom Layer w20: v2(1362,1359) 1541,1359 1571,1389 v2(1571,1467) ; v2@1368.85,1352.15 cw(c1385.38,1335.62) 1385.38,1359 cw(c1385.38,1382.38) v2@1368.85,1365.85 ; v2(1515.75,1851.75) 1709.75,1851.75 1750,1892 v1(1750,2236) v2(1750,2480) ; v2@1522.6,1844.9 cw(c1539.13,1828.37) 1539.13,1851.75 cw(c1539.13,1875.13) v2@1522.6,1858.6 ; v2@1564.15,1460.15 cw(c1547.62,1443.62) 1571,1443.62 cw(c1594.38,1443.62) v2@1577.85,1460.15 ; v2@1743.15,2473.15 cw(c1726.62,2456.62) 1750,2456.62 cw(c1773.38,2456.62) v2@1756.85,2473.15
  other v1: 731,36 1691,36 838,43 948,47 332,48 420,56 244,77 1606,86 1492,92 1367,103 1003,122 209,131 1687,132 301,134 1158,142 832,157 1540,175 1362,194 1638,205 288,211 1012,213 924,223 1632,254 1139,265 1617,324 1234,387 1643,417 244,429 1173,472 1302,472 247,522 1648,527 1099,533 1251,535 642,607 685,608 1663,631 689.69,674.49 477,715 305,725 1677,728 1067,777 1157,823 1670,839 1128,851 771,864 1071,914 278,926 1672,942 1040,943 856,948 1176,1018 489,1021 431,1023 277,1028 1679,1034 275,1132 1684,1132 1033,1134 1249,1151 825,1157 738,1159 1045,1161 526,1172 1064,1189 282,1222 1654,1242 947,1286 984,1301 906,1337 963,1337 1658,1348 1110,1394 1660,1423 805,1476 805,1530 302,1534 237,1539 160,1542 804,1593 182,1614 70,1622 283,1645 777,1668 863,1710 768,1713 1531,1715 62,1719 179,1738 768,1749 863,1769 1529,1773 357,1781 1691,1804 862,1813 1824,1823 968,1832 934,1843 774,1846 185,1848 68,1850 735,1852 759,1875 1152,1883 1327,1883 1225,1886 363,1892 844,1909 1064,1911 810,1927 1151,1936 1227,1938 1326,1938 202,1965 523,1978 581,1981 901,1984 945.5,1984 628,1998 901,2028 945.5,2028 990,2028 367,2041 1214,2066 901,2072 945.5,2072 990,2072 191,2075 1416,2080 1223,2126 1316,2132 1553,2136 1087,2143 1413,2149 371,2154 1123,2165 1694,2169 199,2194 1542,2252 1695,2260 369,2272 200,2275 1415,2293 1318,2300 1538,2400 1834,2433 207,2435 53,2451 263,2519 160,2558 1825,2565 854,2566 54,2569 1018,2573 706,2583 1206,2597 1602,2616 1435,2620 1689,2661 1541,2704 861,2707 1030,2711 1354,2713 1211,2714 378,2723 202,2724 523,2727 712,2728
  other v4: 921.5,1018.1 968.75,1018.1
LINK_LEDG: R33.1 U3.5 | length 510.5
  Top Layer w8: U3.5@1049.04,2039 U3.5@1047.52,2037.48 1447.48,2037.48 1466,2056 R33.1@1466,2087 ; R33.1@1456.45,2087.45 cw(c1433.41,2064.41) 1466,2064.41 cw(c1498.59,2064.41) R33.1@1475.55,2087.45
LINK_LEDR: R32.1 U3.6 | length 406.3
  Top Layer w8: U3.6@1047.52,2057.17 1152.17,2057.17 1190,2095 1357,2095 R32.1@1359,2097 ; 1321.58,2095 ccw(c1321.58,2134.42) R32.1@1349.45,2106.55 ; 1331.24,2095 cw(c1331.24,2069.24) R32.1@1349.45,2087.45 ; 1340.89,2095 ccw(c1340.89,2115.11) R32.1@1355.11,2100.89 ; R32.1@1351,2095 R32.1@1359,2087
LINK_RESET: P1.5 R3.2 R50.2 | length 1056.3
  Top Layer w8: v1@430.76,1723.76 cw(c420.51,1713.51) 435,1713.51 cw(c449.49,1713.51) 439.24,1723.76 cw(c449.49,1713.51) 449.49,1728 cw(c449.49,1742.49) v1@439.24,1732.24 ; R50.2@475.45,1718.45 ccw(c452.41,1695.41) 452.41,1728 ccw(c452.41,1760.59) R50.2@475.45,1737.55 ; R50.2@485,1728 v1(435,1728) 435,1695 509,1621 611,1621 R3.2@678,1554 ; R3.2@664.5,1554 ccw(c631.91,1554) 654.95,1577.05 ccw(c678,1600.09) R3.2@678,1567.5
  Bottom Layer w8: P1.5@64.56,1913.91 cw(c60.38,1902) 73,1902 ; P1.5@73,1938 73,1902 ; P1.5@81.45,1913.91 ccw(c85.62,1902) 73,1902 ; v1@430.76,1723.76 ccw(c420.51,1713.51) 420.51,1728 ccw(c420.51,1742.49) v1@430.76,1732.24 ; v1(435,1728) 247,1728 73,1902
LINK_SWCLK: P1.4 R2.2 R51.2 | length 1365.5
  Top Layer w8: v1(435,1828) 484.5,1828 R51.2@485,1828.5 ; v1@439.24,1823.76 cw(c449.49,1813.51) 449.49,1828 cw(c449.49,1842.49) v1@439.24,1832.24 ; 451.2,1828 ccw(c451.2,1862.3) R51.2@475.45,1838.05 ; 453.62,1828 cw(c453.62,1797.12) R51.2@475.45,1818.95 ; v1@603.76,1706.76 cw(c593.51,1696.51) 608,1696.51 cw(c622.49,1696.51) v1@612.24,1706.76 ; v1(608,1711) 608,1658 656,1610 726,1610 757,1579 757,1549.33 750.67,1543 ; R2.2@753.55,1545.89 ccw(c746.44,1553) R2.2@756.5,1553 ; R2.2@753.69,1546.03 cw(c762,1537.72) R2.2@767.45,1548.13
  Bottom Layer w8: P1.4@73,2012.47 cw(c73,1950.84) 116.58,1994.42 cw(c160.16,2038) P1.4@98.53,2038 ; P1.4@73,2020.47 cw(c73,1978.16) 102.92,2008.08 cw(c132.84,2038) P1.4@90.53,2038 ; P1.4@73,2038 283,1828 v1(435,1828) 486,1777 577,1777 608,1746 v1(608,1711) ; v1@430.76,1823.76 ccw(c420.51,1813.51) 420.51,1828 ccw(c420.51,1842.49) v1@430.76,1832.24 ; v1@435,1822 cw(c435,1807.51) 445.24,1817.76 cw(c455.49,1828) v1@441,1828 ; v1@603.76,1715.24 ccw(c593.51,1725.49) 608,1725.49 ccw(c622.49,1725.49) v1@612.24,1715.24
LINK_SWDIO: P1.3 R1.2 R42.2 R43.2 | length 1728.7
  Top Layer w8: v1(440,1980) 485,1980 ; v1@444.24,1975.76 cw(c454.49,1965.51) 454.49,1980 cw(c454.49,1994.49) v1@444.24,1984.24 ; R42.2@475.45,1938.55 ccw(c452.41,1961.59) 485,1961.59 ccw(c517.59,1961.59) R42.2@494.55,1938.55 ; R43.2@475.45,2019.95 cw(c452.41,1996.91) 485,1996.91 cw(c517.59,1996.91) R43.2@494.55,2019.95 ; R43.2@484.5,2030 R43.2@485,2029.5 ; R42.2@485,1916.33 R42.2@485,1929 485,1980 ; R43.2@485,2020 485,1980 ; v1@656.76,1706.76 cw(c646.51,1696.51) 661,1696.51 cw(c675.49,1696.51) v1@665.24,1706.76 ; v1(661,1711) 661,1657 688,1630 810,1630 857,1583 ; R1.2@847.6,1543 857,1552.4 857,1583 ; R1.2@852.45,1563.55 ccw(c841.48,1574.52) 857,1574.52 ; R1.2@867.69,1566.24 cw(c875.48,1583) 857,1583
  Bottom Layer w8: P1.3@73,2112.47 cw(c73,2050.84) 116.58,2094.42 cw(c160.16,2138) P1.3@98.53,2138 ; P1.3@73,2120.47 cw(c73,2078.16) 102.92,2108.08 cw(c132.84,2138) P1.3@90.53,2138 ; P1.3@73,2138 231,1980 v1(440,1980) 440,1893 506,1827 590,1827 661,1756 v1(661,1711) ; v1@435.76,1984.24 cw(c425.51,1994.49) 425.51,1980 cw(c425.51,1965.51) 435.76,1975.76 cw(c425.51,1965.51) 440,1965.51 cw(c454.49,1965.51) v1@444.24,1975.76 ; v1@656.76,1715.24 ccw(c646.51,1725.49) 661,1725.49 ccw(c675.49,1725.49) v1@665.24,1715.24
LINK_USART_RX: R39.1 R44.1 U3.26 | length 388.2
  Top Layer w8: 895.94,1842.06 908.4,1829.6 R44.1@908.4,1788 R39.1@1002.6,1788 ; 895.94,1844.06 U3.26@895.94,1925.28 ; R44.1@898.85,1797.55 ccw(c875.81,1820.59) 908.4,1820.59 ccw(c940.99,1820.59) 917.95,1797.55 ccw(c940.99,1820.59) 940.99,1788 ccw(c940.99,1755.41) R44.1@917.95,1778.45 ; R39.1@993.05,1778.45 ccw(c970.01,1755.41) 970.01,1788 ccw(c970.01,1820.59) R39.1@993.05,1797.55
LINK_USART_TX: R40.1 R45.1 U3.25 | length 410.8
  Top Layer w8: R40.1@720,1788 R45.1@814.2,1788 814.2,1822.2 876.26,1884.26 U3.25@876.26,1925.28 ; R40.1@729.55,1778.45 cw(c752.59,1755.41) 752.59,1788 cw(c752.59,1820.59) R40.1@729.55,1797.55 ; R45.1@804.65,1778.45 ccw(c781.61,1755.41) 781.61,1788 ccw(c781.61,1820.59) 804.65,1797.55 ccw(c781.61,1820.59) 814.2,1820.59 ccw(c846.79,1820.59) R45.1@823.75,1797.55
LXTAL_IN: C5.2 U1.1 Y1.1 | length 393.6
  Top Layer w8: C5.2@641.58,1184.33 cw(c619.83,1162) 651,1162 ; C5.2@651,1194 651,1162 ; C5.2@660.42,1184.33 ccw(c682.17,1162) 651,1162 ; Y1.1@664.48,1129.46 ccw(c651.14,1142.79) 670,1142.79 ccw(c688.86,1142.79) Y1.1@675.52,1129.46 ; Y1.1@687.33,1118.41 cw(c700.83,1104.91) 700.83,1124 ; Y1.1@687.33,1129.46 ccw(c700.5,1142.63) 700.5,1124 ; U1.1@865.4,1096.84 847.16,1096.84 820,1124 670.07,1124 Y1.1@670,1123.93 670,1143 651,1162
LXTAL_OUT: C6.2 U1.2 Y1.4 | length 427.5
  Top Layer w8: C6.2@643.6,1030.29 ccw(c634.6,1044) 651,1044 ; C6.2@651,1019 651,1044 ; C6.2@658.4,1030.29 cw(c667.4,1044) 651,1044 ; Y1.4@664.48,1082.98 cw(c651.14,1069.64) 670,1069.64 cw(c688.86,1069.64) Y1.4@675.52,1082.98 ; Y1.4@677.41,1081.09 Y1.4@670,1088.5 ; Y1.4@681.7,1088.65 cw(c689.09,1078.82) 697.78,1087.52 ; Y1.4@681.76,1088.68 cw(c687.26,1068.62) 701.97,1083.33 ; Y1.4@686.51,1082.26 cw(c694.68,1071.39) 704.3,1081.01 ; Y1.4@688.21,1084.03 cw(c696.8,1078.02) 696.8,1088.5 ; Y1.4@688.21,1092.97 ccw(c696.8,1098.98) 696.8,1088.5 ; U1.2@865.4,1081.09 704.21,1081.09 696.8,1088.5 ; 651,1044 670,1063 Y1.4@670,1088.5 ; Y1.4@670,1088.5 696.8,1088.5
NetC2_1: C2.1 R11.2 | length 226.9
  Top Layer w8: C2.1@389,1601 447,1601 R11.2@494,1554 ; C2.1@398.55,1591.45 cw(c421.59,1568.41) 421.59,1601 cw(c421.59,1633.59) C2.1@398.55,1610.55 ; R11.2@480.5,1554 ccw(c447.91,1554) 470.95,1577.05 ccw(c494,1600.09) R11.2@494,1567.5
NetC8_2: C8.2 R5.1 | length 199.2
  Top Layer w8: C8.2@945.33,1494 R5.1@1042.17,1494 ; C8.2@963.55,1484.45 cw(c986.59,1461.41) 986.59,1494 cw(c986.59,1526.59) C8.2@963.55,1503.55 ; R5.1@1036.45,1484.45 ccw(c1013.41,1461.41) 1013.41,1494 ccw(c1013.41,1526.59) R5.1@1036.45,1503.55
NetC11_1: C11.1 R19.1 U1.8 Y2.1 | length 1768.3
  Top Layer w8: R19.1@402,548 528.01,548 Y2.1@566,510.01 603.99,548 C11.1@730,548 730,866 850.61,986.61 U1.8@865.4,986.61 ; R19.1@411.55,538.45 cw(c434.59,515.41) 434.59,548 cw(c434.59,580.59) R19.1@411.55,557.55 ; Y2.1@557.07,569.97 ccw(c610.12,623.03) 610.12,548 ; Y2.1@562.73,575.63 ccw(c629.44,642.34) 629.44,548 ; Y2.1@568.38,581.29 ccw(c648.75,661.65) 648.75,548 ; Y2.1@574.04,586.95 ccw(c668.06,680.97) 668.06,548 ; Y2.1@579.7,592.6 ccw(c687.38,700.28) 687.38,548 ; Y2.1@585.35,598.26 ccw(c706.69,719.6) 706.69,548 ; Y2.1@591.01,603.92 ccw(c726,738.91) C11.1@726,548 ; C11.1@720.45,538.45 ccw(c697.41,515.41) 697.41,548 ccw(c697.41,580.59) 720.45,557.55 ccw(c697.41,580.59) 730,580.59 ccw(c762.59,580.59) C11.1@739.55,557.55 ; 846.51,982.51 cw(c856.54,972.49) 856.54,986.67 ccw(c855.17,976.1) 847.64,983.64
NetC12_1: C12.1 R18.1 U1.9 Y2.2 | length 1964.5
  Top Layer w8: R18.1@402,141 560.99,141 Y2.2@566,135.99 ; R18.1@411.55,131.45 cw(c434.59,108.41) 434.59,141 cw(c434.59,173.59) R18.1@411.55,150.55 ; 468.52,141 cw(c468.52,38.52) Y2.2@540.99,110.98 ; 487.84,141 cw(c487.84,57.83) Y2.2@546.65,116.64 ; 492.7,141 ccw(c492.7,209.3) Y2.2@540.99,161 ; 507.15,141 cw(c507.15,77.14) Y2.2@552.3,122.3 ; 512.01,141 ccw(c512.01,189.98) Y2.2@546.65,155.35 ; 526.46,141 cw(c526.46,96.46) Y2.2@557.96,127.95 ; Y2.2@560.99,158 566,152.99 Y2.2@571.01,158 ; Y2.2@570.01,140 683,140 ; Y2.2@579.7,122.3 cw(c622.44,79.56) 622.44,140 cw(c622.41,192.4) Y2.2@585.35,155.35 ; Y2.2@585.35,116.64 cw(c641.75,60.24) 641.75,140 cw(c641.72,211.71) Y2.2@591.01,161 ; Y2.2@591.01,110.98 cw(c661.06,40.93) 661.06,140 ; C12.1@720.45,130.45 ccw(c697.41,107.41) 697.41,140 ccw(c697.41,172.59) C12.1@720.45,149.55 ; C12.1@725.99,135.99 C12.1@730,140 683,140 ; U1.9@890.01,962 890.01,938.01 768,816 768,436 684,352 684,141 683,140
NetC22_2: C22.2 C28.2 U3.32 | length 698.9
  Top Layer w8: U3.32@1014.05,1925.28 1014.05,1885.95 1048,1852 1382,1852 C28.2@1382,1728 ; 1348.8,1852 cw(c1348.8,1818.55) 1372.45,1842.2 cw(c1349.41,1819.16) 1382,1819.16 cw(c1414.59,1819.16) C22.2@1391.55,1842.2 ; 1350.01,1852 ccw(c1350.01,1883.74) C22.2@1372.45,1861.3 ; C28.2@1372.45,1737.55 ccw(c1349.41,1760.59) 1382,1760.59 ccw(c1414.59,1760.59) C28.2@1391.55,1737.55
NetDAPEN_1: DAPEN.1 R6.1 U3.19 | length 1191.6
  Top Layer w8: R6.1@545,2230.5 585.5,2230.5 ; R6.1@554.55,2220.95 cw(c577.59,2197.91) 577.59,2230.5 cw(c577.59,2263.09) R6.1@554.55,2240.05 ; v1@607.76,2282.76 cw(c597.52,2272.51) 612,2272.51 cw(c626.49,2272.51) v1@616.24,2282.76 ; v1(612,2287) 612,2257 585.5,2230.5 ; U3.19@842.8,2057.17 758.83,2057.17 585.5,2230.5
  Bottom Layer w8: DAPEN.1@589.08,2614.08 cw(c533.74,2558.74) 612,2558.74 cw(c690.26,2558.74) DAPEN.1@634.92,2614.08 ; DAPEN.1@594.73,2619.73 cw(c553.05,2578.05) 612,2578.05 cw(c670.95,2578.05) DAPEN.1@629.27,2619.73 ; DAPEN.1@600.39,2625.39 cw(c572.37,2597.37) 612,2597.37 cw(c651.64,2597.37) DAPEN.1@623.61,2625.39 ; v1@607.76,2291.24 ccw(c597.52,2301.49) 612,2301.49 ccw(c626.49,2301.49) v1@616.24,2291.24 ; v1(612,2287) DAPEN.1@612,2637 DAPEN.1@612,2667
NetLED1_1: LED1.1 R14.1 | length 187.9
  Top Layer w8: R14.1@1287.23,852.45 cw(c1264.19,829.41) 1296.78,829.41 cw(c1329.37,829.41) R14.1@1306.33,852.45 ; LED1.1@1289,774.78 ccw(c1270.22,793.56) 1296.78,793.56 ccw(c1323.34,793.56) LED1.1@1304.56,774.78 ; LED1.1@1296.78,767 R14.1@1296.78,862
NetLED2_1: LED2.1 R35.1 | length 228.3
  Top Layer w10: R35.1@1275.16,1340.16 cw(c1253.82,1318.82) 1284,1318.82 cw(c1314.18,1318.82) R35.1@1292.84,1340.16 ; LED2.1@1276.93,1213.07 ccw(c1259.86,1230.14) 1284,1230.14 ccw(c1308.14,1230.14) LED2.1@1291.07,1213.07 ; LED2.1@1284,1206 R35.1@1284,1349
NetLED3_2: LED3.2 R33.2 | length 211.9
  Top Layer w8: R33.2@1456.45,2166.55 ccw(c1433.41,2189.59) 1466,2189.59 ccw(c1498.59,2189.59) R33.2@1475.55,2166.55 ; LED3.2@1458.22,2268.22 cw(c1439.44,2249.44) 1466,2249.44 cw(c1492.56,2249.44) LED3.2@1473.78,2268.22 ; R33.2@1466,2157 LED3.2@1466,2276
NetLED4_2: LED4.2 R32.2 | length 211.9
  Top Layer w8: R32.2@1349.45,2166.55 ccw(c1326.41,2189.59) 1359,2189.59 ccw(c1391.59,2189.59) R32.2@1368.55,2166.55 ; LED4.2@1351.22,2268.22 cw(c1332.44,2249.44) 1359,2249.44 cw(c1385.56,2249.44) LED4.2@1366.78,2268.22 ; R32.2@1359,2157 LED4.2@1359,2276
NetR42_1: R42.1 U3.22 | length 377.6
  Top Layer w8: R42.1@545,1929 609,1929 678.11,1998.11 U3.22@842.8,1998.11 ; R42.1@554.55,1919.45 cw(c577.59,1896.41) 577.59,1929 cw(c577.59,1961.59) R42.1@554.55,1938.55
NetR43_1: R43.1 U3.21 | length 353.8
  Top Layer w8: R43.1@545,2029.5 689.3,2029.5 701,2017.8 U3.21@842.8,2017.8 ; R43.1@554.55,2019.95 cw(c577.59,1996.91) 577.59,2029.5 cw(c577.59,2062.09) R43.1@554.55,2039.05
NetR50_1: R50.1 U3.24 | length 465.7
  Top Layer w8: R50.1@545,1728 590,1728 636,1774 636,1810 784.74,1958.74 U3.24@842.8,1958.74 ; R50.1@554.55,1718.45 cw(c577.59,1695.41) 577.59,1728 cw(c577.59,1760.59) R50.1@554.55,1737.55
NetR51_1: R51.1 U3.23 | length 411.1
  Top Layer w8: R51.1@545,1828.5 595.5,1828.5 745.43,1978.43 U3.23@842.8,1978.43 ; R51.1@554.55,1818.95 cw(c577.59,1795.91) 577.59,1828.5 cw(c577.59,1861.09) R51.1@554.55,1838.05
NRST: B1.2 R3.1 R7.2 R11.1 U1.7 | length 1948.3
  Top Layer w8: v1(357,1181) 427.66,1181 B1.2@428,1180.66 469.66,1180.66 679,1390 R3.1@679,1477 ; v1@361.24,1176.76 cw(c371.49,1166.51) 371.49,1181 cw(c371.49,1195.49) v1@361.24,1185.24 ; 389.32,1181 cw(c389.32,1141.98) B1.2@416.91,1169.57 ; 390.95,1181 ccw(c390.95,1217.71) B1.2@416.91,1191.75 ; B1.2@434.66,1181 B1.2@435,1180.66 ; B1.2@439.09,1169.57 cw(c465.87,1142.79) 465.87,1180.66 cw(c465.87,1218.53) B1.2@439.09,1191.75 ; R11.1@494,1494 554,1554 ; R11.1@494,1507.5 ccw(c494,1540.09) 517.05,1517.05 ccw(c540.09,1494) R11.1@507.5,1494 ; R7.2@576.33,1544.58 ccw(c554,1522.83) 554,1554 ; R7.2@576.33,1563.42 cw(c554,1585.17) 554,1554 ; R7.2@595.67,1544.58 cw(c618,1522.83) 618,1554 ; R7.2@595.67,1563.42 ccw(c618,1585.17) 618,1554 ; R3.1@664.5,1494 ccw(c631.91,1494) 654.95,1517.05 ccw(c678,1540.09) R3.1@678,1507.5 ; R3.1@668.45,1484.45 cw(c642.99,1458.99) 679,1458.99 ; R3.1@678,1494 618,1554 ; 679,1463.82 cw(c708.18,1463.82) R3.1@687.55,1484.45 ; v1(734,902) 834.35,1002.35 U1.7@865.4,1002.35 ; v1@734,908 ccw(c734,922.49) 744.24,912.24 ccw(c754.49,902) v1@740,902 ; 554,1554 R7.2@586,1554 618,1554
  Bottom Layer w8: v1@352.76,1176.76 cw(c342.51,1166.51) 357,1166.51 cw(c371.49,1166.51) v1@361.24,1176.76 ; v1(357,1181) 357,1028 429,956 680,956 v1(734,902) ; v1@728,902 ccw(c713.51,902) 723.76,912.24 ccw(c734,922.49) v1@734,908
PA0: C7.2 C36.2 P2.12 U1.6 | length 1729.5
  Top Layer w8: C36.2@504,674.5 v1(547,674.5) C7.2@591,674.5 635.5,630 681,630 714,663 714,865 705,874 705,906 817.1,1018.1 U1.6@865.4,1018.1 ; C36.2@513.55,664.95 cw(c536.59,641.91) 536.59,674.5 cw(c536.59,707.09) C36.2@513.55,684.05 ; v1@542.76,670.26 ccw(c532.51,660.01) 532.51,674.5 ccw(c532.51,688.99) v1@542.76,678.74 ; v1@551.24,670.26 cw(c561.49,660.01) 561.49,674.5 cw(c561.49,688.99) v1@551.24,678.74 ; C7.2@581.45,664.95 ccw(c558.41,641.91) 558.41,674.5 ccw(c558.41,707.09) C7.2@581.45,684.05 ; C7.2@591,661 cw(c591,628.41) 614.05,651.45 cw(c637.09,674.5) C7.2@604.5,674.5
  Bottom Layer w8: P2.12@73,429 88,429 268,609 481.5,609 v1(547,674.5) ; P2.12@73,430.53 ccw(c73,470.43) 101.21,442.21 ; P2.12@73,438.53 ccw(c73,497.74) 114.87,455.87 ; P2.12@73,446.53 ccw(c73,525.06) 128.53,469.53 ; P2.12@73,454.53 ccw(c73,552.37) 142.18,483.18 ; P2.12@98.53,429 cw(c123.94,429) 105.97,446.97 ; v1@541,674.5 cw(c526.51,674.5) 536.76,664.26 cw(c547,654.01) v1@547,668.5
PA1: P2.8 R40.2 U1.10 | length 2924
  Top Layer w8: P2.8@73,829 162,918 v1(162,1480) ; P2.8@73,846.53 ccw(c73,888.84) 102.92,858.92 ccw(c132.84,829) P2.8@90.53,829 ; P2.8@73,854.53 ccw(c73,916.16) 116.58,872.58 ccw(c160.16,829) P2.8@98.53,829 ; v1@157.76,1475.76 cw(c147.51,1465.51) 162,1465.51 cw(c176.49,1465.51) v1@166.24,1475.76 ; R40.2@710.45,1718.45 cw(c687.41,1695.41) 720,1695.41 cw(c752.59,1695.41) R40.2@729.55,1718.45 ; v1@715.76,1658.24 ccw(c705.51,1668.49) 720,1668.49 ccw(c734.48,1668.48) v1@724.24,1658.24 ; v1(720,1654) R40.2@720,1728 ; v1(804,811) 905.76,912.76 U1.10@905.76,962 ; v1@804,817 ccw(c804,831.49) 814.24,821.24 ccw(c824.49,811) v1@810,811
  Bottom Layer w8: P2.8@78,834 144.29,834 ; P2.8@79.9,822.43 cw(c106.92,796.66) 106.92,834 ; P2.8@85.39,841.39 ccw(c103.24,859.24) 103.24,834 ; P2.8@85.69,816.91 cw(c125.6,778.85) 125.6,834 ; P2.8@91.05,847.05 ccw(c122.56,878.56) 122.56,834 ; P2.8@91.48,811.38 cw(c144.28,761.04) 144.28,834 ; v1@162,1481 163,1480 654,1480 720,1546 v1(720,1654) ; v1@166.24,1475.76 cw(c176.49,1465.51) 176.49,1480 cw(c176.49,1494.49) v1@166.24,1484.24 ; v1@715.76,1649.76 cw(c705.51,1639.51) 720,1639.51 cw(c734.49,1639.51) v1@724.24,1649.76 ; v1@799.76,806.76 ccw(c789.51,796.51) 789.51,811 ccw(c789.51,825.49) v1@799.76,815.24 ; v1(804,811) 167.29,811 144.29,834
